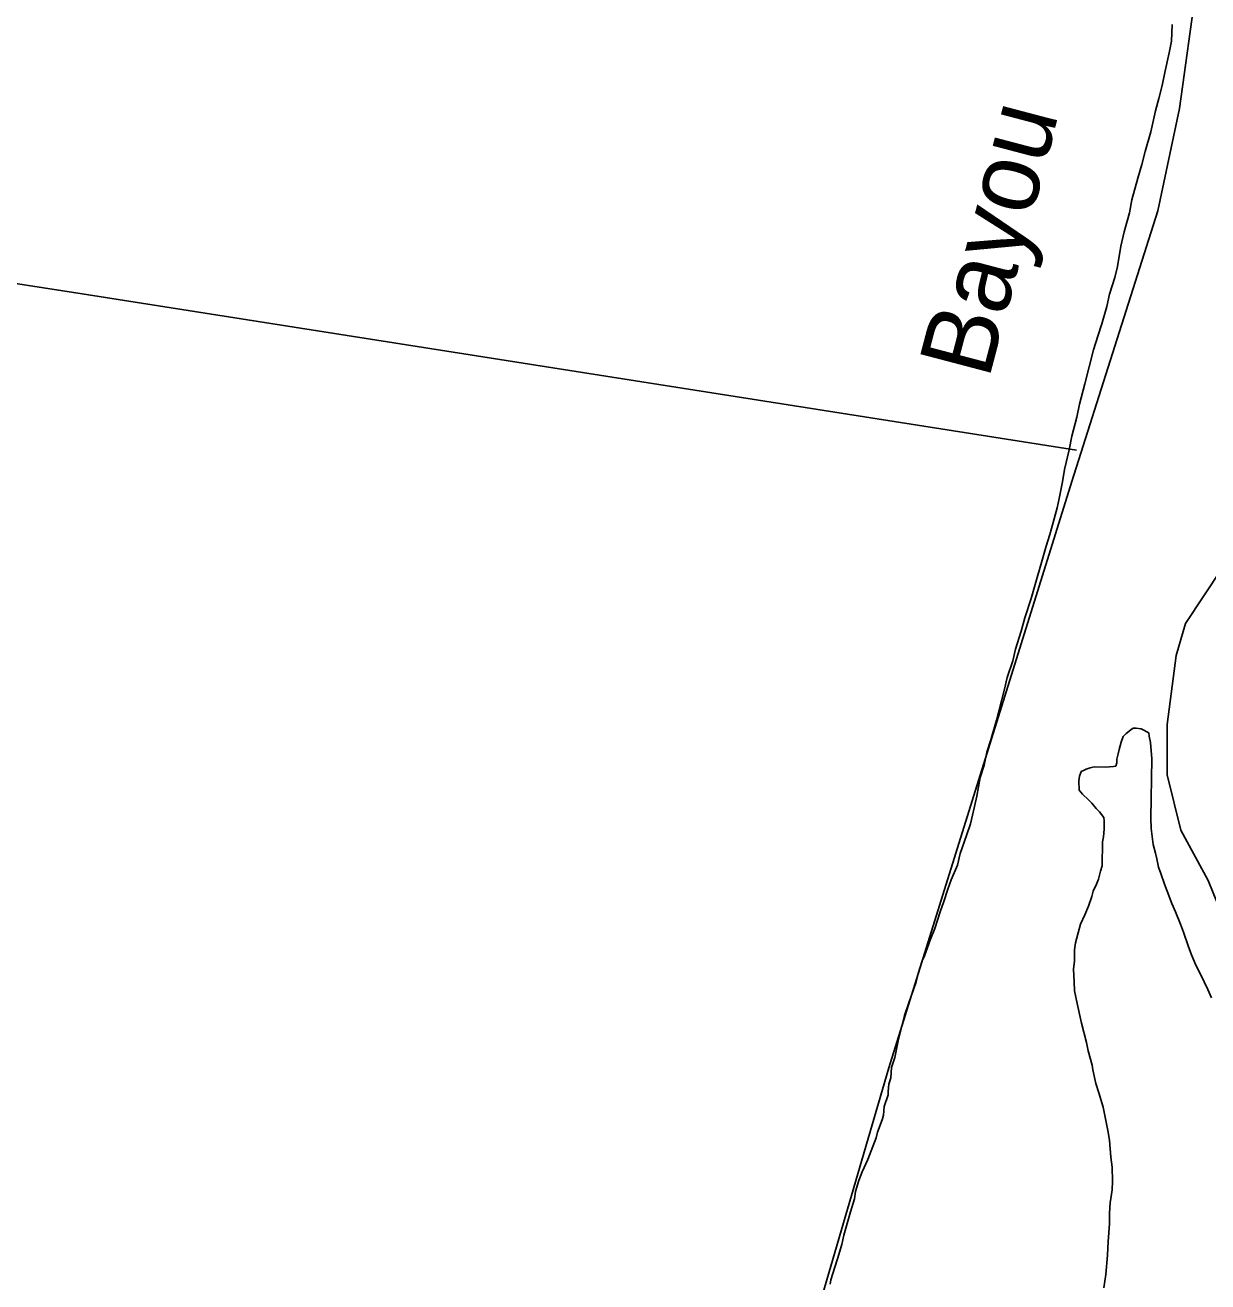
# Model space of a CAD drawing. Extents: x 3161514 to 3199414, y 831166 to 856601.
# Drawn here: x 3169026 to 3170653, y 840836 to 842565 of the extents above; entities that cross this region are included whole.
import ezdxf

# ---------------------------------------------------------------- set-up
doc = ezdxf.new("R2010")
doc.units = 0
for name, color, linetype in [('V-RIVR-IDEN', 7, 'Continuous'), ('V-SITE-VEGE', 7, 'Continuous'), ('V-TOPO-SHOR', 7, 'Continuous')]:
    doc.layers.add(name, color=color, linetype=linetype)

msp = doc.modelspace()

# ---------------------------------------------------------------- linework, layer by layer
at = {"layer": 'V-SITE-VEGE'}
for p, q in [((3170603.2, 842542.9), (3170604.3, 842565.9)), ((3170600.4, 842526.8), (3170603.2, 842542.9)), ((3170594.1, 842499.6), (3170600.4, 842526.8)), ((3170590.4, 842481.7), (3170594.1, 842499.6)), ((3170585.9, 842463.9), (3170590.4, 842481.7)), ((3170581.4, 842446.9), (3170585.9, 842463.9)), ((3170575, 842418), (3170581.4, 842446.9)), ((3170567, 842390.9), (3170575, 842418)), ((3170562.5, 842373.1), (3170567, 842390.9)), ((3170557.1, 842354.4), (3170562.5, 842373.1)), ((3170549, 842324.7), (3170557.1, 842354.4)), ((3170545.4, 842306.8), (3170549, 842324.7)), ((3170538.2, 842280.5), (3170545.4, 842306.8)), ((3170533.7, 842261), (3170538.2, 842280.5)), ((3170529, 842232.9), (3170533.7, 842261)), ((3170525.4, 842217.6), (3170529, 842232.9)), ((3170518.3, 842194.7), (3170525.4, 842217.6)), ((3170514.6, 842177.7), (3170518.3, 842194.7)), ((3170507.5, 842154), (3170514.6, 842177.7)), ((3170502.1, 842137), (3170507.5, 842154)), ((3170495.9, 842118.3), (3170502.1, 842137)), ((3170484.2, 842071.6), (3170495.9, 842118.3)), ((3170477, 842043.6), (3170484.2, 842071.6)), ((3170473.3, 842025.8), (3170477, 842043.6)), ((3170466.2, 841999.5), (3170473.3, 842025.8)), ((3170462.5, 841980.8), (3170466.2, 841999.5)), ((3170456.2, 841953.6), (3170462.5, 841980.8)), ((3170453.4, 841936.6), (3170456.2, 841953.6)), ((3170448.8, 841913.6), (3170453.4, 841936.6)), ((3170440.7, 841880.5), (3170446.1, 841900.9)), ((3170446.1, 841900.9), (3170448.8, 841913.6)), ((3170436.2, 841864.4), (3170440.7, 841880.5)), ((3170430.8, 841848.3), (3170436.2, 841864.4)), ((3170410.2, 841776.1), (3170430.8, 841848.3)), ((3170401.4, 841749.8), (3170410.2, 841776.1)), ((3170396.8, 841731.1), (3170401.4, 841749.8)), ((3170388.8, 841706.5), (3170396.8, 841731.1)), ((3170385.2, 841690.4), (3170388.8, 841706.5)), ((3170377.2, 841667.5), (3170385.2, 841690.4)), ((3170373.6, 841651.4), (3170377.2, 841667.5)), ((3170362.8, 841608.9), (3170373.6, 841651.4)), ((3170354.7, 841581.8), (3170362.8, 841608.9)), ((3170540.9, 841590.7), (3170536.9, 841586.2)), ((3170547.5, 841595.7), (3170540.9, 841590.7)), ((3170550.7, 841597.6), (3170547.5, 841595.7)), ((3170554.6, 841597.6), (3170550.7, 841597.6)), ((3170561.7, 841596.8), (3170554.6, 841597.6)), ((3170572, 841591.5), (3170561.7, 841596.8)), ((3170572.6, 841587), (3170572, 841591.5)), ((3170349.4, 841564.8), (3170354.7, 841581.8)), ((3170534.2, 841578.4), (3170531.5, 841568.7)), ((3170536.9, 841586.2), (3170534.2, 841578.4)), ((3170574.4, 841577.9), (3170572.6, 841587)), ((3170576.1, 841555.8), (3170574.4, 841577.9)), ((3170345.7, 841546.9), (3170349.4, 841564.8)), ((3170528.1, 841555.2), (3170528, 841550)), ((3170530.1, 841562.3), (3170528.1, 841555.2)), ((3170531.5, 841568.7), (3170530.1, 841562.3)), ((3170574.9, 841474.2), (3170576.1, 841555.8)), ((3170340.4, 841530), (3170345.7, 841546.9)), ((3170479.3, 841538.4), (3170476.6, 841531.9)), ((3170482.5, 841539.6), (3170479.3, 841538.4)), ((3170485.8, 841541.5), (3170482.5, 841539.6)), ((3170491.6, 841543.4), (3170485.8, 841541.5)), ((3170496.8, 841544.6), (3170491.6, 841543.4)), ((3170512.4, 841544.4), (3170496.8, 841544.6)), ((3170523.4, 841544.9), (3170512.4, 841544.4)), ((3170526.7, 841545.5), (3170523.4, 841544.9)), ((3170528, 841550), (3170526.7, 841545.5)), ((3170335.8, 841504.5), (3170340.4, 841530)), ((3170476.6, 841531.9), (3170475.8, 841525.4)), ((3170475.8, 841525.4), (3170476.3, 841512.5)), ((3170332.2, 841490), (3170335.8, 841504.5)), ((3170476.3, 841512.5), (3170480.8, 841507.2)), ((3170480.8, 841507.2), (3170489.1, 841499.3)), ((3170326.7, 841466.3), (3170332.2, 841490)), ((3170489.1, 841499.3), (3170493.6, 841494.7)), ((3170493.6, 841494.7), (3170499.9, 841487.5)), ((3170499.9, 841487.5), (3170504.4, 841482.9)), ((3170504.4, 841482.9), (3170510.1, 841475.1)), ((3170510.1, 841475.1), (3170510.7, 841470.5)), ((3170510.7, 841470.5), (3170510.6, 841458.8)), ((3170575.4, 841459.9), (3170574.9, 841474.2)), ((3170321.4, 841450.1), (3170326.7, 841466.3)), ((3170510.6, 841458.8), (3170509.8, 841448.5)), ((3170578.3, 841437.8), (3170575.4, 841459.9)), ((3170312.5, 841425.5), (3170321.4, 841450.1)), ((3170508.4, 841441.4), (3170507.9, 841408.3)), ((3170509.8, 841448.5), (3170508.4, 841441.4)), ((3170581.4, 841426.1), (3170578.3, 841437.8)), ((3170308.9, 841409.4), (3170312.5, 841425.5)), ((3170583.2, 841418.3), (3170581.4, 841426.1)), ((3170585.7, 841406.6), (3170583.2, 841418.3)), ((3170300.1, 841389.1), (3170308.9, 841409.4)), ((3170505.9, 841401.2), (3170503.1, 841390.2)), ((3170507.9, 841408.3), (3170505.9, 841401.2)), ((3170588.8, 841398.1), (3170585.7, 841406.6)), ((3170295.7, 841376.4), (3170300.1, 841389.1)), ((3170500.4, 841383.2), (3170495.8, 841373.5)), ((3170503.1, 841390.2), (3170500.4, 841383.2)), ((3170593.8, 841383.2), (3170588.8, 841398.1)), ((3170597.5, 841373.4), (3170593.8, 841383.2)), ((3170290.3, 841359.4), (3170295.7, 841376.4)), ((3170493.7, 841366.4), (3170489, 841352.8)), ((3170495.8, 841373.5), (3170493.7, 841366.4)), ((3170603.8, 841356.5), (3170597.5, 841373.4)), ((3170285, 841345), (3170290.3, 841359.4)), ((3170489, 841352.8), (3170484.3, 841341.2)), ((3170608.8, 841345.4), (3170603.8, 841356.5)), ((3170277.9, 841322.1), (3170285, 841345)), ((3170484.3, 841341.2), (3170478.3, 841328.4)), ((3170615.7, 841328.4), (3170608.8, 841345.4)), ((3170271.7, 841307.7), (3170277.9, 841322.1)), ((3170474.9, 841316.1), (3170471.5, 841302.5)), ((3170478.3, 841328.4), (3170474.9, 841316.1)), ((3170620.1, 841317.3), (3170615.7, 841328.4)), ((3170626.3, 841298.5), (3170620.1, 841317.3)), ((3170263.7, 841284.8), (3170271.7, 841307.7)), ((3170471.5, 841302.5), (3170470, 841292.8)), ((3170630.7, 841286.1), (3170626.3, 841298.5)), ((3170260.2, 841278), (3170263.7, 841284.8)), ((3170470, 841292.8), (3170469.8, 841277.9)), ((3170637, 841271.7), (3170630.7, 841286.1)), ((3170254.9, 841260.2), (3170260.2, 841278)), ((3170469.8, 841277.9), (3170468.4, 841266.3)), ((3170468.4, 841266.3), (3170469.4, 841248.8)), ((3170643.3, 841259.3), (3170637, 841271.7)), ((3170241.5, 841218.6), (3170252.2, 841249.1)), ((3170252.2, 841249.1), (3170254.9, 841260.2)), ((3170469.4, 841248.8), (3170469.9, 841236.4)), ((3170653.4, 841238.5), (3170643.3, 841259.3)), ((3170469.9, 841236.4), (3170473.6, 841218.9)), ((3170658.4, 841226.7), (3170653.4, 841238.5)), ((3170236.2, 841202.5), (3170241.5, 841218.6)), ((3170473.6, 841218.9), (3170479.7, 841192.2)), ((3170227.2, 841167.7), (3170236.2, 841202.5)), ((3170479.7, 841192.2), (3170486.4, 841165.6)), ((3170222.6, 841144.7), (3170227.2, 841167.7)), ((3170486.4, 841165.6), (3170488.9, 841153.9)), ((3170218.2, 841131.2), (3170222.6, 841144.7)), ((3170488.9, 841153.9), (3170494.4, 841134.3)), ((3170217.1, 841116.7), (3170218.2, 841131.2)), ((3170494.4, 841134.3), (3170495, 841127.9)), ((3170495, 841127.9), (3170499.3, 841109)), ((3170213.4, 841098), (3170214.4, 841108.2)), ((3170214.4, 841108.2), (3170217.1, 841116.7)), ((3170499.3, 841109), (3170503.6, 841096)), ((3170208, 841077.6), (3170213.4, 841093.7)), ((3170213.4, 841093.7), (3170213.4, 841098)), ((3170503.6, 841096), (3170509.2, 841076.5)), ((3170207, 841065.7), (3170208, 841077.6)), ((3170509.2, 841076.5), (3170515.9, 841044.6)), ((3170199, 841042), (3170205.2, 841058.9)), ((3170205.2, 841058.9), (3170207, 841065.7)), ((3170197.2, 841034.3), (3170199, 841042)), ((3170515.9, 841044.6), (3170518.3, 841031)), ((3170190.2, 841016.5), (3170197.2, 841034.3)), ((3170518.3, 841031), (3170519.9, 841007.6)), ((3170177.8, 840987.7), (3170185.7, 841004.6)), ((3170185.7, 841004.6), (3170190.2, 841016.5)), ((3170519.9, 841007.6), (3170521.7, 840994)), ((3170173.4, 840975.8), (3170177.8, 840987.7)), ((3170521.7, 840994), (3170522, 840974.5)), ((3170168.9, 840960.6), (3170173.4, 840975.8)), ((3170522, 840974.5), (3170521.9, 840962.9)), ((3170161.7, 840932.5), (3170167.1, 840950.4)), ((3170167.1, 840950.4), (3170168.9, 840960.6)), ((3170521.9, 840962.9), (3170519, 840944.8)), ((3170519, 840944.8), (3170518.2, 840930.5)), ((3170152.8, 840900.3), (3170161.7, 840932.5)), ((3170518, 840916.2), (3170516.4, 840891.6)), ((3170518.2, 840930.5), (3170518, 840916.2)), ((3170150, 840887.5), (3170152.8, 840900.3)), ((3170143.8, 840868), (3170150, 840887.5)), ((3170516.4, 840891.6), (3170515.4, 840872.9)), ((3170140.2, 840856.2), (3170143.8, 840868)), ((3170515.4, 840872.9), (3170513.1, 840846.3)), ((3170134.9, 840839.2), (3170140.2, 840856.2)), ((3170513.1, 840846.3), (3170510.3, 840828.2)), ((3170133.9, 840833.2), (3170134.9, 840839.2))]:
    msp.add_line(p, q, dxfattribs=at)
at = {"layer": 'V-TOPO-SHOR'}
for points in [[(3170661, 842788.2), (3170614.2, 842450.2), (3170584.6, 842309.6), (3170466.2, 841937.1), (3170214.6, 841130.5), (3170032, 840506.4), (3170017.2, 840499), (3169997.5, 840499), (3169521.4, 840570.6), (3169383.3, 840592.8), (3168482.9, 840728.4)], [(3170868.8, 842607.2), (3170875.1, 842512.4), (3170856.2, 842417.7), (3170824.6, 842323), (3170774, 842196.6), (3170748.8, 842139.8), (3170729.8, 842051.4), (3170717.2, 841994.5), (3170698.3, 841918.8), (3170673, 841817.7), (3170622.5, 841741.9), (3170609.8, 841697.7), (3170597.2, 841603), (3170597.2, 841533.5), (3170616.1, 841457.7), (3170654, 841388.2), (3170679.3, 841325.1), (3170717.2, 841243), (3170793, 841192.4), (3170894, 841129.3), (3170925.6, 841097.7), (3170982.5, 841009.3), (3170995.1, 840984)], [(3167245.1, 842488.8), (3167510.3, 842454), (3167513.5, 842441.4), (3167639.8, 842422.4), (3167721.9, 842409.8), (3169105.1, 842195.1), (3170472.5, 841980.3)]]:
    msp.add_lwpolyline(points, dxfattribs=at)

# ---------------------------------------------------------------- texts
at = {"layer": 'V-RIVR-IDEN'}
msp.add_text('Bayou', height=100, rotation=75.2564, dxfattribs=at).set_placement((3170351.9, 842076.2))

doc.saveas('drawing.dxf')
